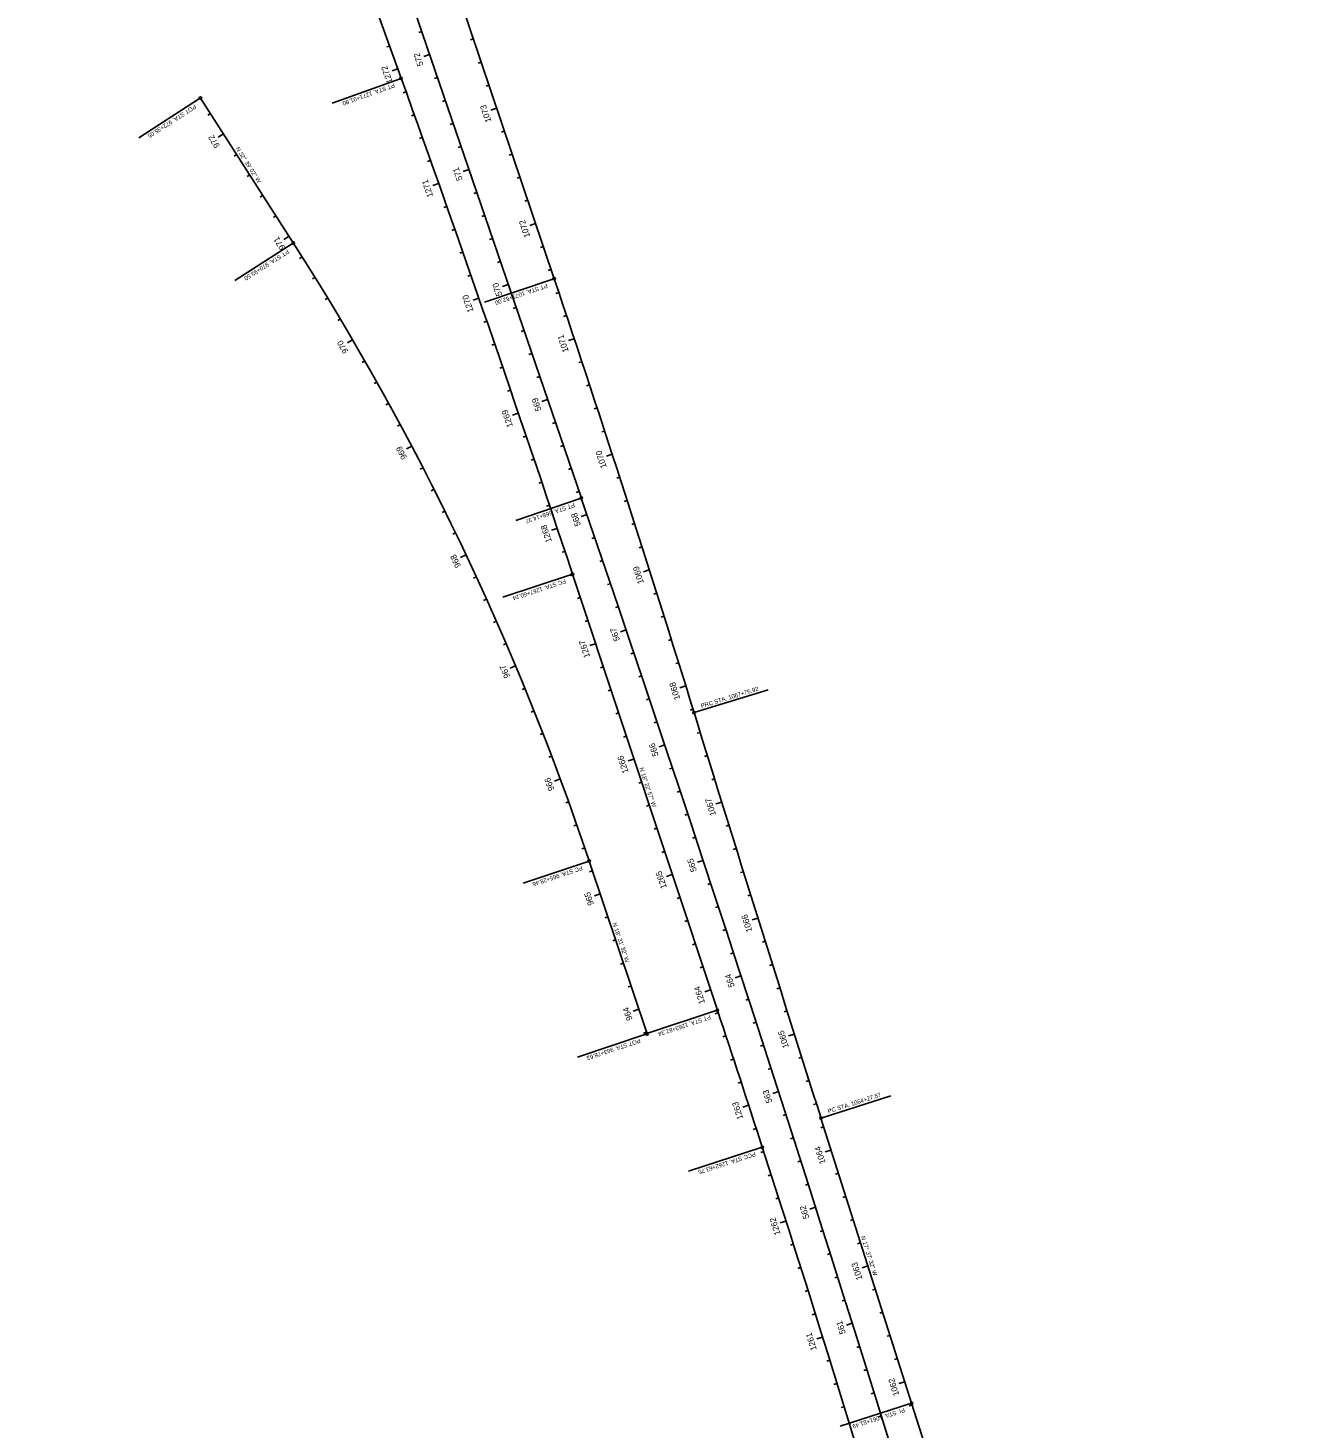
# Model space of a CAD drawing. Extents: x 919452 to 931278, y 583254 to 665650.
# Drawn here: x 929188 to 930225, y 631990 to 633142 of the extents above; entities that cross this region are included whole.
import ezdxf

# ---------------------------------------------------------------- set-up
doc = ezdxf.new("R2010")
doc.units = 0
for name, color, linetype in [('CLConst_dp', 7, 'Continuous'), ('CurveDataLabel_dp', 7, 'Continuous'), ('StationTicL_dp', 7, 'Continuous'), ('StationTicS_dp', 7, 'Continuous'), ('TextBLStation', 7, 'Continuous'), ('TextLabel', 7, 'Continuous')]:
    doc.layers.add(name, color=color, linetype=linetype)

msp = doc.modelspace()

# ---------------------------------------------------------------- linework, layer by layer
at = {"layer": 'CLConst_dp'}
for p, q in [((929494.7, 633100.4), (929187.7, 633955.1)), ((929643, 632755.1), (929294, 633774.4)), ((929620.6, 632935.5), (929379.1, 633652.5)), ((929406, 632964.9), (929329.6, 633084.1)), ((929754.9, 632333.9), (929635.7, 632692.5)), ((929697, 632314.5), (929649.4, 632456.6)), ((929914.7, 632010.7), (929840.1, 632245.2)), ((929981.1, 631803.6), (929914.7, 632010.7))]:
    msp.add_line(p, q, dxfattribs=at)
for centre, radius, start, end in [((912577, 627023.7), 17976, 18.38238, 19.75791), ((927476.2, 631728.4), 2292, 18.5255, 32.6507), ((915678, 628240), 14712, 17.1514, 18.61214), ((902539.3, 623476.4), 28647.9, 14.89045, 18.89818), ((970064.9, 645025.1), 42206.1, 197.1514, 197.62565), ((915541.2, 627610.5), 14978, 17.92872, 18.38238), ((915541.2, 627610.5), 14978, 15.74941, 17.92872)]:
    msp.add_arc(centre, radius, start, end, dxfattribs=at)
at = {"layer": 'CurveDataLabel_dp'}
for p, q in [((929493.8, 633100), (929437.9, 633080)), ((929328.8, 633083.6), (929278.8, 633051.5)), ((929405.2, 632964.4), (929357.9, 632934.1)), ((929619.6, 632935.2), (929563.4, 632916.3)), ((929642, 632754.8), (929589, 632736.6)), ((929634.8, 632692.2), (929578.4, 632673.5)), ((929736.7, 632578.9), (929796.8, 632597.4)), ((929648.5, 632456.3), (929595.1, 632438.4)), ((929753.9, 632333.6), (929697.7, 632314.9)), ((929696.1, 632314.2), (929639.7, 632295.3)), ((929841.1, 632245.5), (929897.6, 632263.5)), ((929790.9, 632220.9), (929731.2, 632201.6)), ((929913.7, 632010.4), (929855.8, 631991.8))]:
    msp.add_line(p, q, dxfattribs=at)
for centre in [(929494.7, 633100.4), (929329.6, 633084.1), (929406, 632964.9), (929620.6, 632935.5), (929643, 632755.1), (929635.7, 632692.5), (929735.7, 632578.6), (929649.4, 632456.6), (929754.9, 632333.9), (929697, 632314.5), (929840.1, 632245.2), (929791.8, 632221.2), (929914.7, 632010.7)]:
    msp.add_circle(centre, 1, dxfattribs=at)
at = {"layer": 'StationTicL_dp'}
for p, q in [((929518.1, 633120), (929513.3, 633118.3)), ((929491.9, 633108.1), (929487.2, 633106.4)), ((929573.3, 633075.8), (929568.6, 633074.2)), ((929348.5, 633054.6), (929344.3, 633051.9)), ((929550.5, 633025.4), (929545.7, 633023.7)), ((929525.5, 633013.9), (929520.8, 633012.2)), ((929605.3, 632981), (929600.5, 632979.4)), ((929402.5, 632970.4), (929398.3, 632967.7)), ((929582.8, 632930.7), (929578.1, 632929.1)), ((929558.6, 632919.5), (929553.9, 632917.9)), ((929637.1, 632886.2), (929632.3, 632884.6)), ((929454.8, 632885.2), (929450.5, 632882.7)), ((929615.2, 632836.1), (929610.5, 632834.5)), ((929591.1, 632825), (929586.4, 632823.4)), ((929503.4, 632797.8), (929499, 632795.5)), ((929668.3, 632791.2), (929663.6, 632789.7)), ((929647.6, 632741.5), (929642.9, 632739.9)), ((929623.1, 632730.2), (929618.4, 632728.6)), ((929548.1, 632708.4), (929543.6, 632706.2)), ((929698.9, 632696), (929694.2, 632694.5)), ((929679.8, 632646.8), (929675.1, 632645.2)), ((929654.7, 632635.3), (929650, 632633.8)), ((929588.9, 632617.1), (929584.3, 632615.1)), ((929728.9, 632600.6), (929724.1, 632599.1)), ((929711.6, 632552.1), (929706.9, 632550.5)), ((929686.2, 632540.4), (929681.5, 632538.9)), ((929625.6, 632524.1), (929620.9, 632522.3)), ((929758.5, 632505.1), (929753.7, 632503.6)), ((929743.2, 632457.1), (929738.4, 632455.6)), ((929717.8, 632445.5), (929713, 632444)), ((929658.5, 632429.6), (929653.7, 632428)), ((929788.3, 632409.6), (929783.5, 632408.1)), ((929774.3, 632362.1), (929769.6, 632360.6)), ((929749.3, 632350.7), (929744.6, 632349.1)), ((929690.2, 632334.8), (929685.5, 632333.2)), ((929818.3, 632314.2), (929813.5, 632312.7)), ((929805.2, 632267), (929800.4, 632265.5)), ((929780.6, 632255.7), (929775.9, 632254.1)), ((929848.5, 632218.9), (929843.7, 632217.4)), ((929835.7, 632171.8), (929830.9, 632170.3)), ((929811.3, 632160.5), (929806.6, 632159)), ((929878.8, 632123.6), (929874, 632122.1)), ((929865.9, 632076.4), (929861.1, 632074.9)), ((929841.4, 632065.1), (929836.6, 632063.6)), ((929909, 632028.3), (929904.3, 632026.8))]:
    msp.add_line(p, q, dxfattribs=at)
at = {"layer": 'StationTicS_dp'}
for p, q in [((929511.6, 633138.9), (929509.2, 633138.1)), ((929554.2, 633132.7), (929551.8, 633131.9)), ((929485.2, 633126.9), (929482.8, 633126.1)), ((929560.6, 633113.7), (929558.2, 633112.9)), ((929524.5, 633101), (929522.2, 633100.2)), ((929567, 633094.7), (929564.6, 633093.9)), ((929498.7, 633089.3), (929496.3, 633088.4)), ((929531, 633082.1), (929528.7, 633081.3)), ((929337.8, 633071.4), (929335.6, 633070.1)), ((929505.4, 633070.4), (929503.1, 633069.6)), ((929537.5, 633063.2), (929535.1, 633062.4)), ((929512.1, 633051.6), (929509.8, 633050.8)), ((929579.7, 633056.8), (929577.3, 633056)), ((929359.3, 633037.8), (929357.2, 633036.4)), ((929544, 633044.3), (929541.6, 633043.5)), ((929586.1, 633037.9), (929583.7, 633037.1)), ((929518.8, 633032.8), (929516.5, 633031.9)), ((929370.1, 633020.9), (929368, 633019.6)), ((929592.5, 633018.9), (929590.1, 633018.1)), ((929380.9, 633004.1), (929378.8, 633002.7)), ((929556.9, 633006.4), (929554.6, 633005.6)), ((929532.2, 632995), (929529.8, 632994.2)), ((929598.9, 633000), (929596.5, 632999.2)), ((929391.7, 632987.3), (929389.6, 632985.9)), ((929563.4, 632987.5), (929561, 632986.7)), ((929538.8, 632976.2), (929536.4, 632975.3)), ((929569.9, 632968.6), (929567.5, 632967.8)), ((929545.4, 632957.3), (929543.1, 632956.5)), ((929611.6, 632962.1), (929609.3, 632961.3)), ((929413.3, 632953.6), (929411.1, 632952.2)), ((929576.4, 632949.7), (929574, 632948.9)), ((929618, 632943.1), (929615.6, 632942.3)), ((929423.9, 632936.6), (929421.7, 632935.3)), ((929552, 632938.4), (929549.6, 632937.6)), ((929624.4, 632924.2), (929622, 632923.4)), ((929434.3, 632919.6), (929432.2, 632918.3)), ((929589.3, 632911.8), (929587, 632911)), ((929444.7, 632902.4), (929442.5, 632901.1)), ((929565.1, 632900.6), (929562.8, 632899.8)), ((929630.7, 632905.2), (929628.4, 632904.4)), ((929595.8, 632892.9), (929593.4, 632892.1)), ((929571.7, 632881.7), (929569.3, 632880.9)), ((929602.3, 632874), (929599.9, 632873.2)), ((929464.8, 632867.9), (929462.7, 632866.7)), ((929578.2, 632862.8), (929575.8, 632862)), ((929643.4, 632867.2), (929641, 632866.5)), ((929608.8, 632855.1), (929606.4, 632854.3)), ((929474.7, 632850.5), (929472.5, 632849.3)), ((929584.6, 632843.9), (929582.3, 632843.1)), ((929649.7, 632848.3), (929647.3, 632847.5)), ((929484.4, 632833), (929482.2, 632831.8)), ((929655.9, 632829.3), (929653.5, 632828.5)), ((929621.7, 632817.2), (929619.3, 632816.4)), ((929494, 632815.5), (929491.8, 632814.3)), ((929597.6, 632806), (929595.2, 632805.2)), ((929662.1, 632810.2), (929659.8, 632809.5)), ((929628.2, 632798.3), (929625.8, 632797.5)), ((929604, 632787.1), (929601.6, 632786.3)), ((929512.7, 632780.1), (929510.4, 632778.9)), ((929634.7, 632779.4), (929632.3, 632778.6)), ((929674.5, 632772.2), (929672.1, 632771.4)), ((929521.8, 632762.3), (929519.5, 632761.1)), ((929610.4, 632768.1), (929608, 632767.3)), ((929641.1, 632760.5), (929638.8, 632759.6)), ((929616.8, 632749.2), (929614.4, 632748.4)), ((929680.7, 632753.2), (929678.3, 632752.4)), ((929530.7, 632744.4), (929528.5, 632743.3)), ((929539.5, 632726.4), (929537.2, 632725.3)), ((929686.8, 632734.1), (929684.4, 632733.4)), ((929654.1, 632722.6), (929651.7, 632721.8)), ((929692.9, 632715.1), (929690.5, 632714.3)), ((929629.5, 632711.3), (929627.1, 632710.5)), ((929660.5, 632703.7), (929658.2, 632702.9)), ((929556.6, 632690.3), (929554.3, 632689.2)), ((929635.8, 632692.3), (929633.4, 632691.5)), ((929667, 632684.7), (929664.6, 632683.9)), ((929564.9, 632672.1), (929562.6, 632671)), ((929642.1, 632673.3), (929639.7, 632672.5)), ((929705, 632677), (929702.6, 632676.2)), ((929673.4, 632665.8), (929671, 632665)), ((929711, 632657.9), (929708.6, 632657.1)), ((929573.1, 632653.8), (929570.8, 632652.8)), ((929648.4, 632654.3), (929646, 632653.5)), ((929581.1, 632635.5), (929578.8, 632634.5)), ((929717, 632638.8), (929714.6, 632638.1)), ((929686.2, 632627.9), (929683.8, 632627.1)), ((929661, 632616.4), (929658.6, 632615.6)), ((929723, 632619.7), (929720.6, 632619)), ((929596.6, 632598.6), (929594.2, 632597.6)), ((929692.6, 632608.9), (929690.2, 632608.1)), ((929667.3, 632597.4), (929664.9, 632596.6)), ((929698.9, 632590), (929696.6, 632589.2)), ((929604.1, 632580.1), (929601.8, 632579.1)), ((929673.6, 632578.4), (929671.3, 632577.6)), ((929734.8, 632581.5), (929732.4, 632580.8)), ((929705.3, 632571), (929702.9, 632570.2)), ((929611.4, 632561.5), (929609.1, 632560.6)), ((929679.9, 632559.4), (929677.6, 632558.6)), ((929740.7, 632562.4), (929738.3, 632561.7)), ((929618.6, 632542.8), (929616.3, 632541.9)), ((929746.6, 632543.3), (929744.3, 632542.6)), ((929718, 632533.1), (929715.6, 632532.3)), ((929692.5, 632521.5), (929690.2, 632520.7)), ((929752.6, 632524.2), (929750.2, 632523.5)), ((929724.3, 632514.1), (929721.9, 632513.3)), ((929632.5, 632505.3), (929630.1, 632504.4)), ((929698.9, 632502.5), (929696.5, 632501.7)), ((929730.6, 632495.1), (929728.2, 632494.3)), ((929639.2, 632486.4), (929636.8, 632485.6)), ((929705.2, 632483.5), (929702.8, 632482.7)), ((929764.4, 632486), (929762, 632485.3)), ((929736.9, 632476.1), (929734.5, 632475.4)), ((929645.7, 632467.5), (929643.4, 632466.7)), ((929711.5, 632464.5), (929709.1, 632463.7)), ((929770.4, 632466.9), (929768, 632466.2)), ((929652.1, 632448.6), (929649.7, 632447.8)), ((929749.4, 632438.2), (929747, 632437.4)), ((929776.3, 632447.8), (929773.9, 632447.1)), ((929724.1, 632426.6), (929721.7, 632425.8)), ((929782.3, 632428.7), (929779.9, 632428)), ((929755.7, 632419.2), (929753.3, 632418.4)), ((929664.8, 632410.7), (929662.5, 632409.9)), ((929730.4, 632407.6), (929728, 632406.8)), ((929671.2, 632391.7), (929668.8, 632390.9)), ((929761.9, 632400.2), (929759.5, 632399.4)), ((929794.2, 632390.6), (929791.9, 632389.8)), ((929736.7, 632388.6), (929734.3, 632387.8)), ((929768.1, 632381.1), (929765.8, 632380.4)), ((929677.5, 632372.7), (929675.2, 632371.9)), ((929743, 632369.6), (929740.6, 632368.8)), ((929800.2, 632371.5), (929797.9, 632370.7)), ((929683.9, 632353.8), (929681.5, 632353)), ((929806.2, 632352.4), (929803.9, 632351.6)), ((929780.5, 632343.1), (929778.2, 632342.3)), ((929812.2, 632333.3), (929809.9, 632332.6)), ((929755.6, 632331.7), (929753.2, 632330.9)), ((929786.7, 632324.1), (929784.3, 632323.3)), ((929696.6, 632315.8), (929694.2, 632315)), ((929761.9, 632312.7), (929759.5, 632311.9)), ((929792.9, 632305.1), (929790.5, 632304.3)), ((929768.2, 632293.7), (929765.8, 632292.9)), ((929824.3, 632295.2), (929821.9, 632294.4)), ((929799, 632286), (929796.7, 632285.3)), ((929830.3, 632276.1), (929827.9, 632275.4)), ((929774.4, 632274.7), (929772, 632273.9)), ((929836.4, 632257), (929834, 632256.3)), ((929811.3, 632248), (929808.9, 632247.2)), ((929786.8, 632236.7), (929784.4, 632235.9)), ((929842.4, 632238), (929840, 632237.2)), ((929793, 632217.6), (929790.6, 632216.9)), ((929817.4, 632228.9), (929815.1, 632228.2)), ((929823.5, 632209.9), (929821.2, 632209.1)), ((929799.1, 632198.6), (929796.7, 632197.8)), ((929854.5, 632199.9), (929852.2, 632199.1)), ((929829.6, 632190.8), (929827.3, 632190.1)), ((929805.2, 632179.6), (929802.9, 632178.8)), ((929860.6, 632180.8), (929858.2, 632180)), ((929866.7, 632161.7), (929864.3, 632161)), ((929841.8, 632152.7), (929839.4, 632152)), ((929817.4, 632141.5), (929815, 632140.7)), ((929872.7, 632142.7), (929870.3, 632141.9)), ((929847.8, 632133.7), (929845.4, 632132.9)), ((929823.4, 632122.4), (929821, 632121.6)), ((929853.9, 632114.6), (929851.5, 632113.8)), ((929829.4, 632103.3), (929827.1, 632102.6)), ((929884.8, 632104.6), (929882.4, 632103.8)), ((929859.9, 632095.5), (929857.5, 632094.8)), ((929835.4, 632084.2), (929833, 632083.5)), ((929890.9, 632085.5), (929888.5, 632084.7)), ((929871.9, 632057.4), (929869.5, 632056.6)), ((929896.9, 632066.4), (929894.6, 632065.7)), ((929847.3, 632046), (929844.9, 632045.3)), ((929903, 632047.4), (929900.6, 632046.6)), ((929877.9, 632038.3), (929875.5, 632037.5)), ((929853.2, 632026.9), (929850.8, 632026.2)), ((929883.8, 632019.2), (929881.5, 632018.5)), ((929859.1, 632007.8), (929856.7, 632007.1)), ((929889.8, 632000.1), (929887.4, 631999.4)), ((929915.1, 632009.2), (929912.7, 632008.5))]:
    msp.add_line(p, q, dxfattribs=at)

# ---------------------------------------------------------------- texts
at = {"layer": 'CurveDataLabel_dp'}
for s, rotation, p in [('PT STA. 1271+91.80', 199.7579, (929488.7, 633096.4)), ('POT STA. 972+35.05', 212.6507, (929324.7, 633078.9)), ('PT STA. 970+93.50', 212.6507, (929401, 632959.7)), ('PT STA. 1071+52.00', 198.6121, (929614.5, 632931.6)), ('PT STA. 568+14.37', 198.8982, (929636.9, 632751.2)), ('PC STA. 1267+60.24', 198.3824, (929629.6, 632688.6)), ('PRC STA. 1067+76.92', 17.1514, (929741.9, 632582.3)), ('PC STA. 965+28.46', 198.5255, (929643.3, 632452.7)), ('PT STA. 1263+82.34', 198.3824, (929748.8, 632330)), ('POT STA. 963+78.63', 198.5255, (929690.9, 632310.7)), ('PC STA. 1064+27.57', 17.6256, (929846.3, 632249)), ('PCC STA. 1262+63.75', 197.9287, (929785.7, 632217.4)), ('PI  STA. 1061+81.49', 197.7943, (929908.5, 632006.9))]:
    msp.add_text(s, height=3.5, rotation=rotation, dxfattribs=at).set_placement(p)
at = {"layer": 'TextBLStation'}
for s, rotation, p in [('572', 108.8982, (929513.1, 633111.3)), ('1272', 109.7579, (929487.9, 633097.2)), ('1073', 108.6121, (929569, 633065)), ('972', 122.6507, (929345.8, 633045)), ('571', 108.8982, (929545.4, 633017.1)), ('1271', 109.4653, (929521.2, 633003.5)), ('1072', 108.6121, (929601, 632970.3)), ('971', 122.6507, (929399.5, 632961.2)), ('570', 108.8982, (929577.9, 632922.1)), ('1270', 109.1466, (929554.4, 632908.8)), ('1071', 108.4096, (929632.6, 632875.9)), ('970', 120.3132, (929451.6, 632875.8)), ('569', 108.8982, (929610.3, 632827.5)), ('1269', 108.8278, (929586.8, 632814.2)), ('969', 117.8134, (929499.8, 632788.5)), ('1070', 108.0202, (929663.9, 632780.6)), ('568', 108.8694, (929642.7, 632732.9)), ('1268', 108.5091, (929618.8, 632719.5)), ('968', 115.3136, (929544.1, 632699.2)), ('1069', 107.6307, (929694.5, 632685.4)), ('567', 108.6694, (929674.8, 632638.3)), ('1267', 108.3824, (929650.3, 632624.7)), ('967', 112.8138, (929584.5, 632608.2)), ('1068', 107.2413, (929724.4, 632590)), ('566', 108.4694, (929706.6, 632543.5)), ('1266', 108.3824, (929681.9, 632529.7)), ('966', 110.314, (929620.9, 632515.3)), ('1067', 107.2558, (929753.9, 632494.6)), ('1265', 108.3824, (929713.4, 632434.8)), ('565', 108.2694, (929738.1, 632448.6)), ('965', 108.5255, (929653.4, 632421)), ('1066', 107.3916, (929783.7, 632399)), ('564', 108.0694, (929769.2, 632353.6)), ('1264', 108.3824, (929744.9, 632340)), ('964', 108.5255, (929685.2, 632326.3)), ('1065', 107.5273, (929813.8, 632303.6)), ('563', 107.8694, (929800.1, 632258.4)), ('1263', 108.0674, (929776.2, 632245)), ('1064', 107.6256, (929844, 632208.3)), ('562', 107.6694, (929830.6, 632163.2)), ('1262', 107.6849, (929806.9, 632149.8)), ('1063', 107.6256, (929874.3, 632112.9)), ('1261', 107.3023, (929836.7, 632054.9)), ('561', 107.4694, (929860.6, 632068.3)), ('1062', 107.6256, (929904.6, 632017.6))]:
    msp.add_text(s, height=5, rotation=rotation, dxfattribs=at).set_placement(p)
at = {"layer": 'TextLabel'}
for s, rotation, p in [('N 32%%d 39\' 02" W', 302.6507, (929358.4, 633042.5)), ('N 18%%d 22\' 57" W', 288.3824, (929690.6, 632532.9)), ('N 18%%d 31\' 32" W', 288.5255, (929668.5, 632405.3)), ('N 17%%d 37\' 32" W', 287.6256, (929872.9, 632147.7))]:
    msp.add_text(s, height=3.5, rotation=rotation, dxfattribs=at).set_placement(p)

doc.saveas('drawing.dxf')
